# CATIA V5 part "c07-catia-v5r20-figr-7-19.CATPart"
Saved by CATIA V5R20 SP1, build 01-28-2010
Part number: Part2
Bounding box of the stored display mesh (mm): x -50 to 50, y -65 to 65, z 0 to 28
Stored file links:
  D:\v5_r20\psrt_files_downloaded\c07-catia-v5r20-prt\c07-catia-v5r20-figr-7-19.CATPart
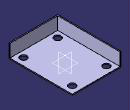
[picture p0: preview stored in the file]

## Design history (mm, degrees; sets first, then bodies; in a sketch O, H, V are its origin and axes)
Body1 (main body)
  Sketch1 on xy-plane, origin (0, 0, 0), H (1, 0, 0), V (0, 1, 0)
    line L1 (-50, 65) -> (50, 65)
    line L2 (50, 65) -> (50, -65)
    line L3 (50, -65) -> (-50, -65)
    line L4 (-50, -65) -> (-50, 65)
    axis line L5 (50, -65) -> (-50, 65)
    length L3 = 100
    length L2 = 130
    horizontal: L1 H, L3 H
    vertical: L2 V, L4 V
    midpoint: O L5
  Pad1: profile Sketch1, direction (0, 0, 1), length 28
  Shell1: IntOffset 2, Face (face of Pad1; face of Pad1; face of Pad1), ExtOffset 0
  Sketch2 on face of Pad1, origin (25.9302, -33.7092, 28), H (1, 0, 0), V (0, 1, 0)
    point P1 (9.0698, -16.2908)
    reference projected line E1 (-75.9302, -31.2908) -> (24.0698, -31.2908) from edge [face of Pad1 | face of Pad1]
    reference projected line E2 (24.0698, -31.2908) -> (24.0698, 98.7092) from edge [face of Pad1 | face of Pad1]
    distance P1 E1 = 15
    distance P1 E2 = 15
  Hole1: placed by Sketch2, at (35, -50, 28) direction (0, 0, -1), diameter 14, through (limit type 3)
  RectPattern1: of Hole1, direction 1 instances 2, spacing 100, along edge [face of Pad1 | face of Pad1], direction 2 instances 2, spacing 70, along edge [face of Pad1 | face of Pad1]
